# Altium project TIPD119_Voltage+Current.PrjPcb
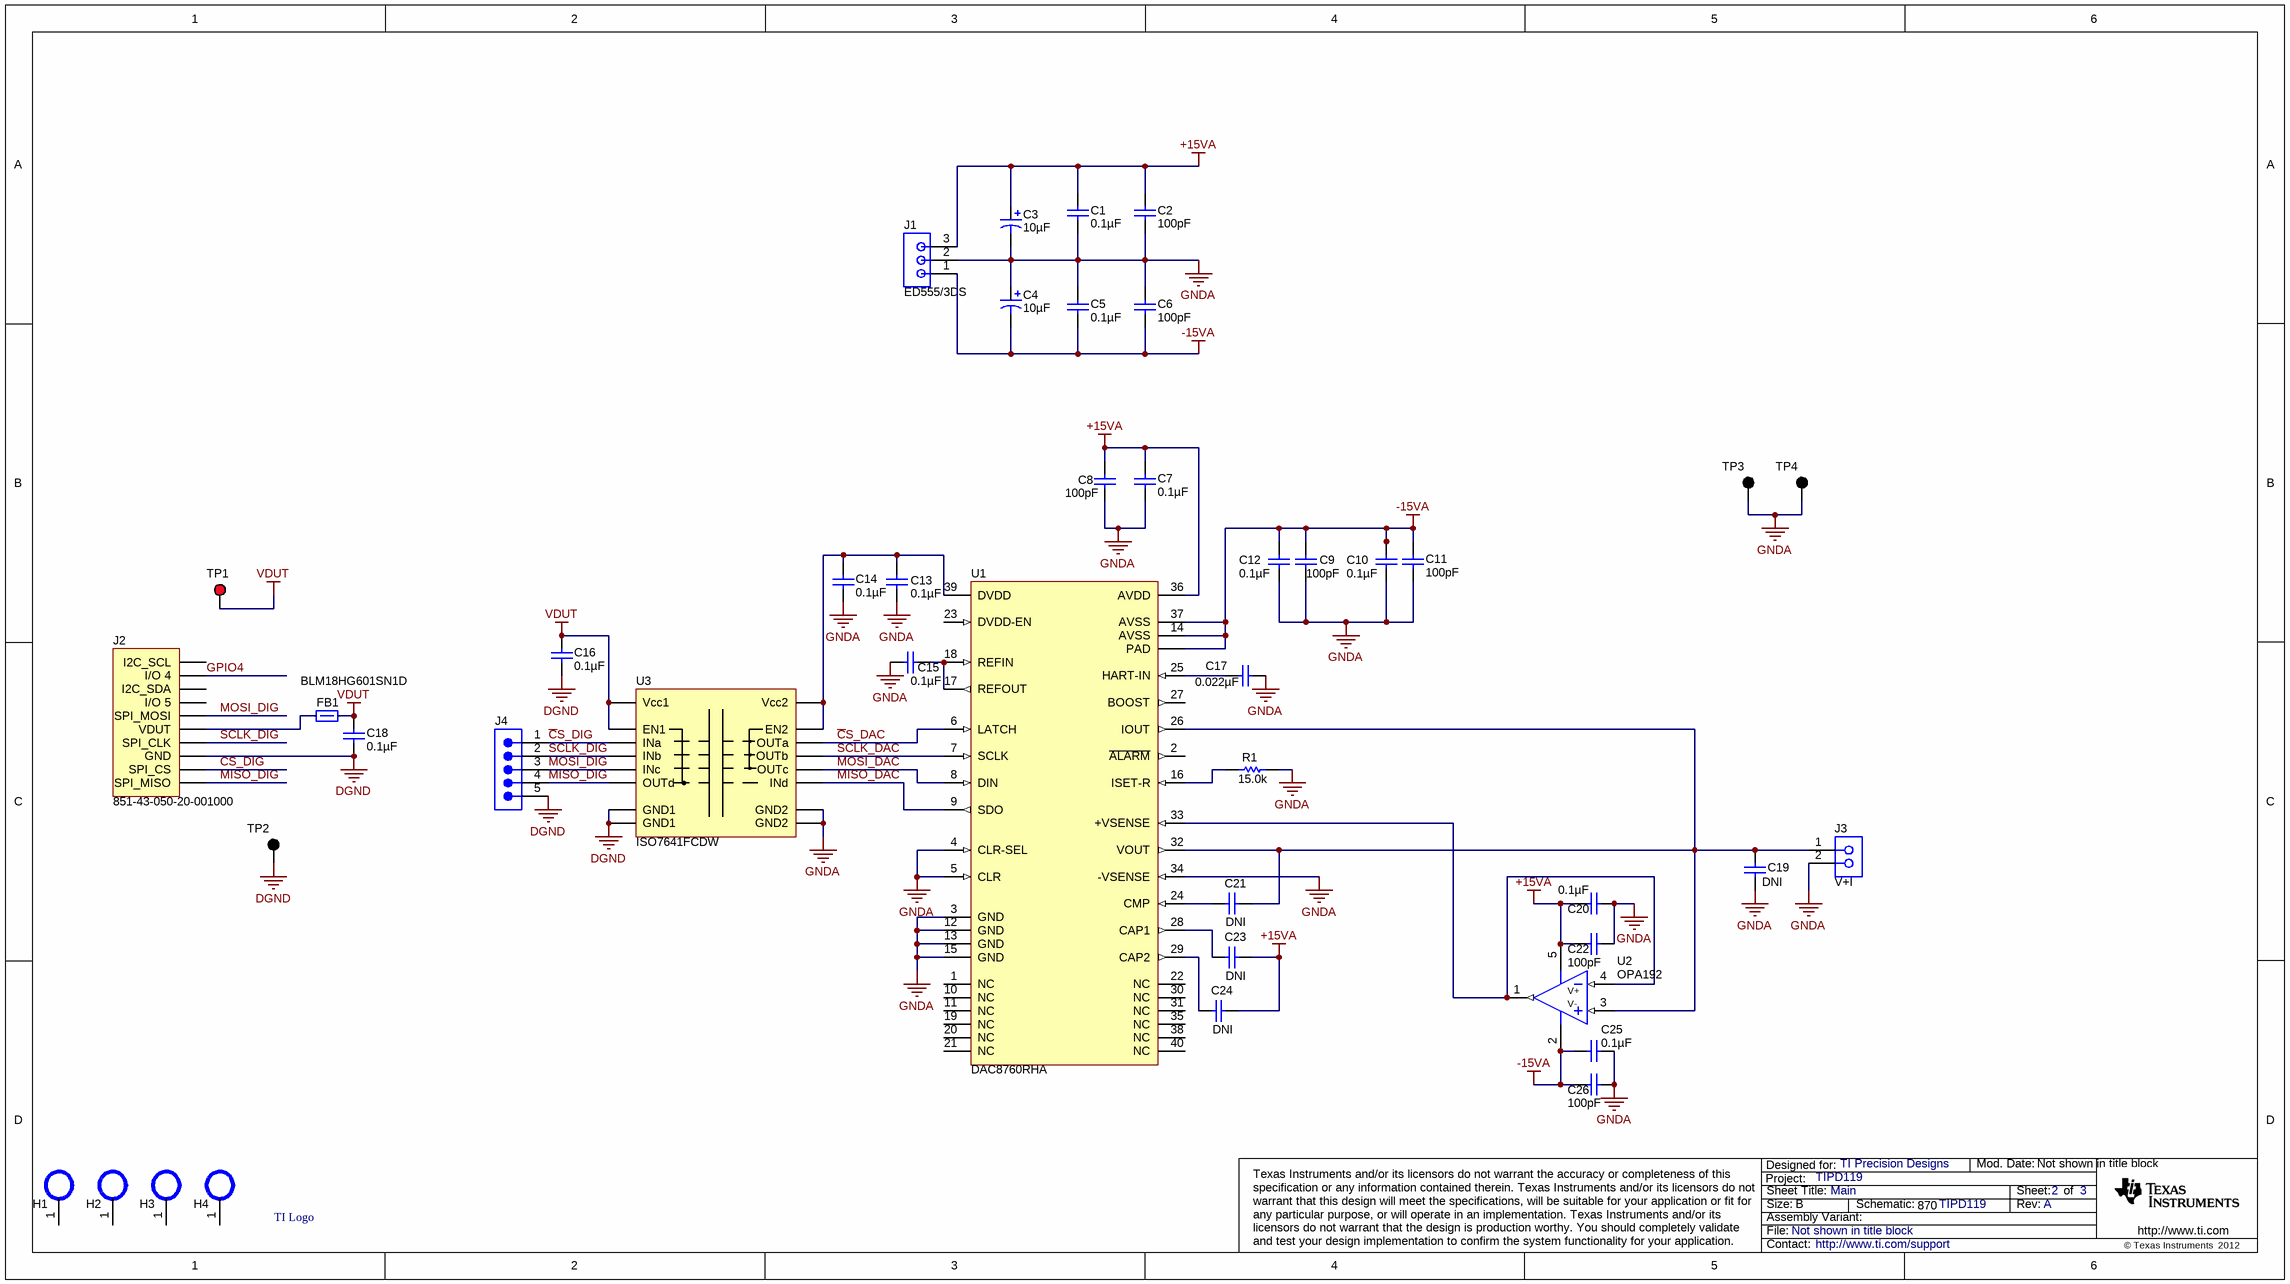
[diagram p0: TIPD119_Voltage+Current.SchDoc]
CopyrightYear: 2012; PCB_CopperRev: 001; PCB_SilkRev: REV A; PRJ_BasePN: TIPD119; PRJ_Customer: TI Precision Designs; PRJ_Title: TIPD119; SCH_Rev: A; TechSupport: http://www.ti.com/support
1 sheet, 44 parts. Net scope: global (net labels, ports and power ports of the same name join across sheets).
Board files: TIPD119_Voltage+Current.PcbDoc, TIPD119_Voltage+Current_ASCII.PcbDoc

## Sheet TIPD119_Voltage+Current.SchDoc: Main
size 431 x 241 mm; VersionControl_RevNumber: A; Date: Not shown in title block; ApprovedBy: Not shown in title block; CheckedBy: Not shown in title block; Author: Not shown in title block; CompanyName: Not shown in title block; DrawnBy: Not shown in title block; Engineer: Not shown in title block; Organization: Not shown in title block; Address1: Not shown in title block; Address2: Not shown in title block; Address3: Not shown in title block; Address4: Not shown in title block; DocumentNumber: 2; Revision: A; SheetNumber: 2; SheetTotal: 3; PageSetup: Record=PageOptions|CenterHorizontal=True|CenterVertical=True|PrintScale=0.96|XCorrection=1.00|YCorrection=1.00|PrintKind=0|BorderSize=5000000|LeftOffset=0|BottomOffset=0|Orientation=2|PaperLength=1000|PaperWidth=1000|Scale=100|PaperSource=259|PrintQuality=600|MediaType=1|DitherType=10|PaperKind=11x17|PrintScaleMode=1

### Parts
C1  ValueDisplayed: 0.1µF  [0603]  (hidden comment: GRM188R71H104KA93D)
C2  ValueDisplayed: 100pF  [0603]  (hidden comment: 06035A101JAT2A)
C3  ValueDisplayed: 10µF  [7343-43]  (hidden comment: 293D106X9050E2TE3)
C4  ValueDisplayed: 10µF  [7343-43]  (hidden comment: 293D106X9050E2TE3)
C5  ValueDisplayed: 0.1µF  [0603]  (hidden comment: GRM188R71H104KA93D)
C6  ValueDisplayed: 100pF  [0603]  (hidden comment: 06035A101JAT2A)
C7  ValueDisplayed: 0.1µF  [0603]  (hidden comment: GRM188R71H104KA93D)
C8  ValueDisplayed: 100pF  [0603]  (hidden comment: 06035A101JAT2A)
C9  ValueDisplayed: 100pF  [0603]  (hidden comment: 06035A101JAT2A)
C10  ValueDisplayed: 0.1µF  [0603]  (hidden comment: GRM188R71H104KA93D)
C11  ValueDisplayed: 100pF  [0603]  (hidden comment: 06035A101JAT2A)
C12  ValueDisplayed: 0.1µF  [0603]  (hidden comment: GRM188R71H104KA93D)
C13  ValueDisplayed: 0.1µF  [0603]  (hidden comment: GRM188R71H104KA93D)
C14  ValueDisplayed: 0.1µF  [0603]  (hidden comment: GRM188R71H104KA93D)
C15  ValueDisplayed: 0.1µF  [0603]  (hidden comment: GRM188R71H104KA93D)
C16  ValueDisplayed: 0.1µF  [0603]  (hidden comment: GRM188R71H104KA93D)
C17  ValueDisplayed: 0.022µF  [0603]  (hidden comment: C1608X7R1H223K)
C18  ValueDisplayed: 0.1µF  [0603]  (hidden comment: GRM188R71H104KA93D)
C19  DNI  [0603]
C20  ValueDisplayed: 0.1µF  [0603]  (hidden comment: GRM188R71H104KA93D)
C21  DNI  [0603]
C22  ValueDisplayed: 100pF  [0603]  (hidden comment: 06035A101JAT2A)
C23  DNI  [0603]
C24  DNI  [0603]
C25  ValueDisplayed: 0.1µF  [0603]  (hidden comment: GRM188R71H104KA93D)
C26  ValueDisplayed: 100pF  [0603]  (hidden comment: 06035A101JAT2A)
FB1  BLM18HG601SN1D  [0603]
H1  NA  [Mounting Hole]  (value not drawn)  (no BOM)
H2  NA  [Mounting Hole]  (value not drawn)  (no BOM)
H3  NA  [Mounting Hole]  (value not drawn)  (no BOM)
H4  NA  [Mounting Hole]  (value not drawn)  (no BOM)
J1  ED555/3DS  [ED555/3DS]
J2  851-43-050-20-001000  [851-43-010-20-001000]
J3  V+I  [ED555/2DS]
J4  TSW-105-07-G-S  [TSW-105-07-G-S]  (value not drawn)
R1  value 15.0k  [0603]  (hidden comment: RG1608P-153-B-T5)
TI1  Texas Instruments logo  [TI LOGO]  (value not drawn)  (no BOM)
TP1  5005  [Keystone5005]  (value not drawn)
TP2  5006  [Keystone5006]  (value not drawn)
TP3  5006  [Keystone5006]  (value not drawn)
TP4  5006  [Keystone5006]  (value not drawn)
U1  DAC8760RHA  [RHA0040C]
U2  OPA192  [MF05A_N]
U3  ISO7641FCDW  [M16B_N]

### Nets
+15VA: C1.2 C2.1 C3.1(+) C7.1 C8.1 C20.1 C22.1 C23.1 C24.1 J1.3 U1.36(AVDD) U2.5(V+)
-15VA: C4.2(-) C5.1 C6.2 C9.2 C10.2 C11.2 C12.2 C25.1 C26.1 J1.1 U1.14(AVSS) U1.37(AVSS) U1.41(PAD) U2.2(V-)
DGND: C16.2 C18.2 J2.8(GND) J4.5 TP2.1 U3.2(GND1) U3.8(GND1)
GNDA: C1.1 C2.2 C3.2(-) C4.1(+) C5.2 C6.1 C7.2 C8.2 C9.1 C10.1 C11.1 C12.1 C13.2 C14.2 C15.2 C17.2 C19.2 C20.2 C22.2 C25.2 C26.2 J1.2 J3.2 R1.1 TP3.1 TP4.1 U1.3(GND) U1.4(CLR-SEL) U1.5(CLR) U1.12(GND) U1.13(GND) U1.15(GND) U1.34(-VSENSE) U3.9(GND2) U3.15(GND2)
VDUT: C16.1 C18.1 FB1.2 TP1.1 U3.1(Vcc1) U3.7(EN1)
~{C}S_DAC: U1.6(LATCH) U3.14(OUTa)
~{C}S_DIG: J2.9(SPI_CS) J4.1 U3.3(INa)
GPIO4: J2.2(I/O_4)
MISO_DAC: U1.9(SDO) U3.11(INd)
MISO_DIG: J2.10(SPI_MISO) J4.4 U3.6(OUTd)
MOSI_DAC: U1.8(DIN) U3.12(OUTc)
MOSI_DIG: J2.5(SPI_MOSI) J4.3 U3.5(INc)
SCLK_DAC: U1.7(SCLK) U3.13(OUTb)
SCLK_DIG: J2.7(SPI_CLK) J4.2 U3.4(INb)
NetC13_1: C13.1 C14.1 U1.39(DVDD) U3.10(EN2) U3.16(Vcc2)
NetC15_1: C15.1 U1.17(REFOUT) U1.18(REFIN)
NetC17_1: C17.1 U1.25(HART-IN)
NetC19_1: C19.1 C21.1 J3.1 U1.26(IOUT) U1.32(VOUT) U2.3(IN+)
NetC21_2: C21.2 U1.24(CMP)
NetC23_2: C23.2 U1.28(CAP1)
NetC24_2: C24.2 U1.29(CAP2)
NetFB1_1: FB1.1 J2.6(VDUT)
NetR1_2: R1.2 U1.16(ISET-R)
NetU1_33: U1.33(+VSENSE) U2.1(OUT) U2.4(IN-)

Not connected (* = marked no-connect by the designer): H1 1; H2 1; H3 1; H4 1; J2 1(I2C_SCL) 3(I2C_SDA) 4(I/O_5); U1 1(NC) 2(~{ALARM}) 10(NC) 11(NC) 19(NC) 20(NC) 21(NC) 22(NC) 23(DVDD-EN) 27(BOOST) 30(NC) 31(NC) 35(NC) 38(NC) 40(NC)

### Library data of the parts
C1 C5 C7 C10 C12-C16 C18 C20 C25 = GRM188R71H104KA93D: CAP, CERM, 0.1uF, 50V, +/-10%, X7R, 0603; Manufacturer: MuRata; Polarized: N; CompType: Capacitor; U/M: EA; Cap_F: 0.0000001; Tolerance_%: 10; VDC_V: 50; TaMin_C: -55; TaMax_C: 125
C2 C6 C8 C9 C11 C22 C26 = 06035A101JAT2A: CAP, CERM, 100pF, 50V, +/-5%, C0G/NP0, 0603; Manufacturer: AVX; Polarized: N; CompType: Capacitor; U/M: EA; Cap_F: 0.0000000001; Tolerance_%: 5; ESR_Ohm: 0.119; Value1: 0.119 ohm; VDC_V: 50; TaMin_C: -55; TaMax_C: 125
C3 C4 = 293D106X9050E2TE3: CAP, TANT, 10uF, 50V, +/-10%, 0.8 ohm, 7343-43 SMD; Manufacturer: Vishay-Sprague; Polarized: Y; CompType: Capacitor; U/M: EA; Cap_F: 0.00001; Tolerance_%: 10; Value1: 0.8 ohm; VDC_V: 50; ESR_Ohm: 0.8; IRMS_A: 0.45; TaMin_C: -55; TaMax_C: 125; Cap_Case: E
C17 = C1608X7R1H223K: CAP, CERM, 0.022uF, 50V, +/-10%, X7R, 0603; Manufacturer: TDK; Polarized: N; CompType: Capacitor; U/M: EA; Cap_F: 0.000000022; Tolerance_%: 10; ESR_Ohm: 0.0383; Value1: 0.0383 ohm; VDC_V: 50; TaMin_C: -55; TaMax_C: 125
C19 C21 C23 C24 = GRM188R72A102KA01D: CAP, CERM, 1000pF, 100V, +/-10%, X7R, 0603; Manufacturer: MuRata; Polarized: N; CompType: Capacitor; U/M: EA; Cap_F: 0.000000001; Tolerance_%: 10; Value1: Unknown; VDC_V: 100; TaMin_C: -55; TaMax_C: 125
FB1 = Ferrite_Bead: FERRITE CHIP 600 OHM 200MA 0603; Manufacturer: MuRata; U/M: EA
H1-H4 = Mounting Hole: Manufacturer: Used in BOM report; SymbolVersion: use current date i.e. 2008-05-20; SymbolCreator: Use LDAP id; CompType: Used in some BOM reports.  Useful for finding later.; U/M: EA, IN, or GM
J1 = 1715734: TERMINAL BLOCK 3.5MM 3POS PCB; Manufacturer: On Shore Technology Inc; SymbolVersion: use current date i.e. 2008-05-20; SymbolCreator: Use LDAP id; U/M: EA, IN, or GM
J2 = SM-USB-DIG-CONN: CONN SOCKET 50PIN .050 R/A SNGL; Manufacturer: Mill-Max Manufacturing Corp.; SymbolCreator: Use LDAP id; U/M: EA, IN, or GM
J3 = 1727010: TERMINAL BLOCK 3.5MM 2POS PCB; Manufacturer: On Shore Technology Inc; U/M: EA; Value: 2x1
J4 = TSW-105-07-G-S: Header, TH, 100mil, 5x1, Gold plated, 230 mil above insulator; Manufacturer: Samtec, Inc.; SymbolCreator: a0412235; U/M: EA
R1 = RG1608P-153-B-T5: RES, 15.0k ohm, 0.1%, 0.1W, 0603; Manufacturer: Susumu Co Ltd; CompType: Resistor; Res_ohm: 15000; Value_Code: 15k0; Tolerance_%: 0.1; VDC_V: 75; TempCo: 25 ppm/C; EIA_Code: E192; U/M: EA
TI1 = TI LOGO: TI BUG
TP1 = 5005: Test Point, Compact, Red, TH; Manufacturer: Keystone; CompType: Test Point Loop; U/M: EA
TP2-TP4 = 5006: Test Point, Compact, Black, TH; Manufacturer: Keystone; CompType: Test Point Loop; U/M: EA
U1 = DAC8760RHA: Single-Channel, 16-Bit Programmable Current Output and Voltage Output DIGITAL-TO-ANALOG CONVERTER for 4-mA to 20-mA Current Loop Applications, RHA0040C; Alternate Manufacturer: None; Manufacturer: Texas Instruments; SymbolCreator: a0411947; CompType: IC; U/M: EA
U2 = LMV721M5: PartNumber: OPA192AIDBVT; Manufacturer: Texas Instruments; CompType: OpAmp IC
U3 = ISO7241: ISOLATOR DGTL 25MBPS 4CH 16SOIC; Manufacturer: Texas Instruments Inc; SymbolVersion: use current date i.e. 2008-05-20; SymbolCreator: Use LDAP id; CompType: Used in some BOM reports.  Useful for finding later.; U/M: EA, IN, or GM

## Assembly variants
-100A: all parts fitted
